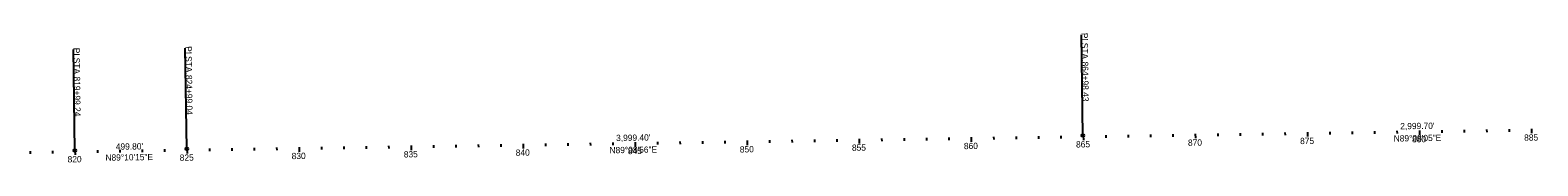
# Model space of a CAD drawing. Extents: x 117326 to 225548, y 573011 to 581051.
# Drawn here: x 198548 to 205275, y 578193 to 578769 of the extents above; entities that cross this region are included whole.
import ezdxf

# ---------------------------------------------------------------- set-up
doc = ezdxf.new("R2010")
doc.units = 0
for name, color, linetype in [('_CIVIL_CONSTRUCTION', 7, 'Continuous'), ('GE_P_Alignment', 7, 'Continuous'), ('GE_P_Alignment_100_Cardinal_Points', 7, 'Continuous'), ('GE_P_Alignment_100_Curve_Data', 7, 'Continuous')]:
    doc.layers.add(name, color=color, linetype=linetype)

msp = doc.modelspace()

# ---------------------------------------------------------------- linework, layer by layer
at = {"layer": 'GE_P_Alignment'}
for p, q in [((203245.5, 578313.5), (203238.7, 578763.4)), ((198746.8, 578246.8), (198740.3, 578696.8)), ((199246.6, 578254.1), (199239.9, 578704))]:
    msp.add_line(p, q, dxfattribs=at)
for centre in [(199246.6, 578254.1), (203245.5, 578313.5), (198746.8, 578246.8)]:
    msp.add_circle(centre, 6, dxfattribs=at)
at = {"layer": 'GE_P_Alignment_100_Curve_Data'}
for p, q in [((204047, 578325.6), (204047.2, 578313.6)), ((204147, 578327.1), (204147.2, 578315.1)), ((204247, 578328.6), (204247.3, 578308.6)), ((204347, 578330.1), (204347.1, 578318.1)), ((204447, 578331.6), (204447.1, 578319.6)), ((204546.9, 578333.1), (204547.1, 578321.1)), ((204646.9, 578334.6), (204647.1, 578322.6)), ((204746.9, 578336.1), (204747.2, 578316.2)), ((204846.9, 578337.7), (204847.1, 578325.7)), ((204946.9, 578339.2), (204947.1, 578327.2)), ((205046.9, 578340.7), (205047.1, 578328.7)), ((205146.9, 578342.2), (205147.1, 578330.2)), ((205246.9, 578343.7), (205247.2, 578323.7)), ((199547.5, 578258.5), (199547.7, 578246.5)), ((199647.5, 578260), (199647.7, 578248)), ((199747.5, 578261.5), (199747.8, 578241.5)), ((199847.5, 578263), (199847.6, 578251)), ((199947.5, 578264.5), (199947.6, 578252.5)), ((200047.4, 578266), (200047.6, 578254)), ((200147.4, 578267.5), (200147.6, 578255.5)), ((200247.4, 578268.9), (200247.7, 578248.9)), ((200347.4, 578270.4), (200347.6, 578258.4)), ((200447.4, 578271.9), (200447.6, 578259.9)), ((200547.4, 578273.4), (200547.6, 578261.4)), ((200647.4, 578274.9), (200647.6, 578262.9)), ((200747.4, 578276.4), (200747.7, 578256.4)), ((200847.4, 578277.8), (200847.5, 578265.8)), ((200947.3, 578279.3), (200947.5, 578267.3)), ((201047.3, 578280.8), (201047.5, 578268.8)), ((201147.3, 578282.3), (201147.5, 578270.3)), ((201247.3, 578283.8), (201247.6, 578263.8)), ((201347.3, 578285.3), (201347.5, 578273.3)), ((201447.3, 578286.8), (201447.5, 578274.8)), ((201547.3, 578288.2), (201547.5, 578276.2)), ((201647.3, 578289.7), (201647.4, 578277.7)), ((201747.3, 578291.2), (201747.6, 578271.2)), ((201847.2, 578292.7), (201847.4, 578280.7)), ((201947.2, 578294.2), (201947.4, 578282.2)), ((202047.2, 578295.7), (202047.4, 578283.7)), ((202147.2, 578297.2), (202147.4, 578285.2)), ((202247.2, 578298.6), (202247.5, 578278.6)), ((202347.2, 578300.1), (202347.4, 578288.1)), ((202447.2, 578301.6), (202447.4, 578289.6)), ((202547.2, 578303.1), (202547.3, 578291.1)), ((202647.2, 578304.6), (202647.3, 578292.6)), ((202747.1, 578306.1), (202747.4, 578286.1)), ((202847.1, 578307.6), (202847.3, 578295.6)), ((202947.1, 578309), (202947.3, 578297)), ((203047.1, 578310.5), (203047.3, 578298.5)), ((203147.1, 578312), (203147.3, 578300)), ((203247.1, 578313.5), (203247.4, 578293.5)), ((203347.1, 578315), (203347.3, 578303)), ((203447.1, 578316.5), (203447.2, 578304.5)), ((203547.1, 578318), (203547.2, 578306)), ((203647, 578319.5), (203647.2, 578307.5)), ((203747, 578321), (203747.3, 578301.1)), ((203847, 578322.6), (203847.2, 578310.6)), ((203947, 578324.1), (203947.2, 578312.1)), ((198547.6, 578243.9), (198547.8, 578231.9)), ((198647.6, 578245.4), (198647.8, 578233.4)), ((198747.6, 578246.8), (198747.9, 578226.8)), ((198847.6, 578248.3), (198847.7, 578236.3)), ((198947.6, 578249.7), (198947.7, 578237.7)), ((199047.5, 578251.2), (199047.7, 578239.2)), ((199147.5, 578252.6), (199147.7, 578240.6)), ((199247.5, 578254.1), (199247.8, 578234.1)), ((199347.5, 578255.6), (199347.7, 578243.6)), ((199447.5, 578257.1), (199447.7, 578245.1))]:
    msp.add_line(p, q, dxfattribs=at)

# ---------------------------------------------------------------- texts
at = {"layer": '_CIVIL_CONSTRUCTION'}
for s, rotation, p in [('N89°08\'56"E', 0.85111, (201133.1, 578234.1)), ('N89°08\'05"E', 0.86525, (204632.3, 578286.4)), ('N89°10\'15"E', 0.82923, (198883.8, 578200.8))]:
    msp.add_text(s, height=28, rotation=rotation, dxfattribs=at).set_placement(p)
at = {"layer": 'GE_P_Alignment'}
for s, rotation, p in [('PI', 270.86525, (203239, 578771.6)), ('PI', 270.82923, (198740.6, 578705)), ('PI', 270.85111, (199240.2, 578712.2)), (' STA. ', 270.85111, (199240.7, 578678.3)), (' STA. ', 270.86525, (203239.5, 578737.7)), (' STA. ', 270.82923, (198741.1, 578671.1)), ('864+98.43', 270.86525, (203241, 578643.2)), ('819+99.24', 270.82923, (198742.5, 578576.6)), ('824+99.04', 270.85111, (199242.1, 578583.8))]:
    msp.add_text(s, height=28, rotation=rotation, dxfattribs=at).set_placement(p)
at = {"layer": 'GE_P_Alignment_100_Cardinal_Points'}
for s, rotation, p in [("2,999.70'", 0.86525, (204661.6, 578341.1)), ("499.80'", 0.82923, (198929.9, 578249.9)), ("3,999.40'", 0.85111, (201162.5, 578288.8))]:
    msp.add_text(s, height=28, rotation=rotation, dxfattribs=at).set_placement(p)
at = {"layer": 'GE_P_Alignment_100_Curve_Data'}
for s, rotation, p in [('845', 0.85111, (201215.1, 578230.3)), ('850', 0.85111, (201714.6, 578237.7)), ('855', 0.85111, (202214.9, 578245.2)), ('860', 0.85111, (202714.5, 578252.6)), ('865', 0.86525, (203214.8, 578260)), ('870', 0.86525, (203714.4, 578267.5)), ('875', 0.86525, (204214.7, 578275.1)), ('880', 0.86525, (204714.3, 578282.7)), ('885', 0.86525, (205214.6, 578290.2)), ('820', 0.82923, (198714.9, 578193.4)), ('825', 0.85111, (199215.3, 578200.6)), ('830', 0.85111, (199714.8, 578208)), ('835', 0.85111, (200215.2, 578215.5)), ('840', 0.85111, (200714.7, 578222.9))]:
    msp.add_text(s, height=28, rotation=rotation, dxfattribs=at).set_placement(p)

doc.saveas('drawing.dxf')
